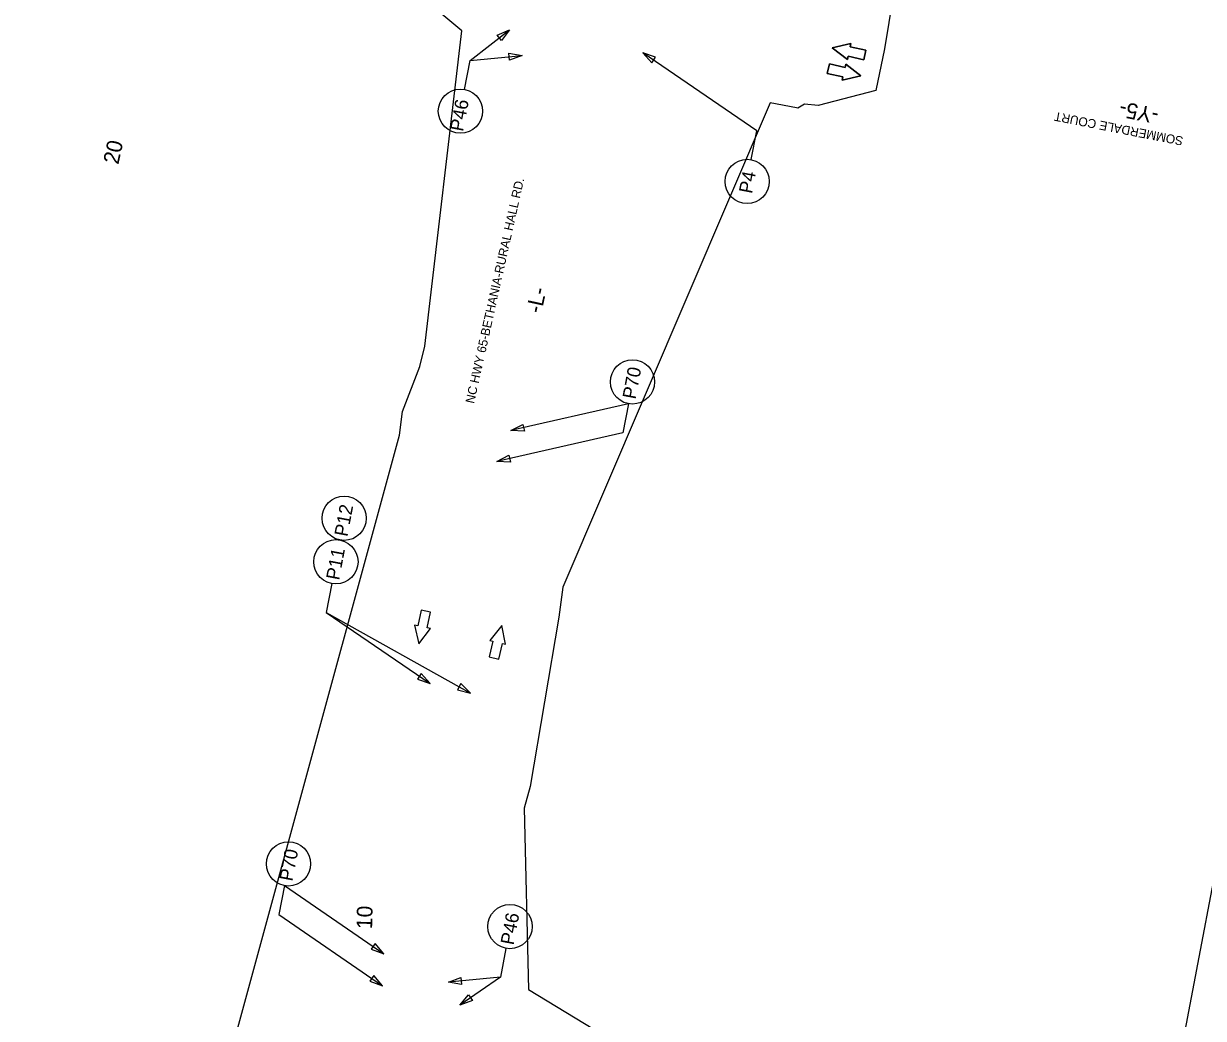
# Model space of a CAD drawing. Extents: x 1615680 to 1617075, y 898420 to 901168.
# Drawn here: x 1616168 to 1616696, y 900256 to 900701 of the extents above; entities that cross this region are included whole.
import ezdxf

# ---------------------------------------------------------------- set-up
doc = ezdxf.new("R2010")
doc.units = 0
for name, color, linetype in [('Default', 7, 'Continuous'), ('DEV DIRECTION OF TRAFFIC FLOW ARROW CELL', 7, 'Continuous'), ('Prop Horizontal Alignment Tick Label', 7, 'Continuous'), ('Scratch_Level_5', 7, 'Continuous'), ('Sheet Cross Section CELL', 7, 'Continuous')]:
    doc.layers.add(name, color=color, linetype=linetype)

msp = doc.modelspace()

# ---------------------------------------------------------------- linework, layer by layer
at = {"layer": 'Default'}
for p, q in [((1616367.82, 900684.55), (1616385.44, 900698.22)), ((1616438.6, 900531.14), (1616386.09, 900519.11)), ((1616303.52, 900437.85), (1616368.06, 900401.87)), ((1616284.79, 900315.8), (1616329.23, 900285.36)), ((1616381.37, 900274.83), (1616363.18, 900262.41))]:
    msp.add_line(p, q, dxfattribs=at)
for points in [[(1616379.91, 900695.89), (1616385.44, 900698.22), (1616381.82, 900693.44)], [(1616385.13, 900687.78), (1616391.05, 900686.79), (1616385.43, 900684.69)], [(1616450.77, 900686.01), (1616445.11, 900688), (1616449.02, 900683.44)], [(1616392.09, 900518.9), (1616386.09, 900519.11), (1616391.4, 900521.92)], [(1616385.84, 900505.08), (1616379.85, 900505.3), (1616385.15, 900508.11)], [(1616344.26, 900408.07), (1616349.92, 900406.08), (1616346.02, 900410.63)], [(1616362.24, 900403.34), (1616368.06, 900401.87), (1616363.75, 900406.05)], [(1616323.57, 900287.36), (1616329.23, 900285.36), (1616325.33, 900289.92)], [(1616323.07, 900273.08), (1616328.73, 900271.08), (1616324.82, 900275.64)], [(1616364.06, 900271.6), (1616358.14, 900272.59), (1616363.76, 900274.69)], [(1616368.84, 900264.4), (1616363.18, 900262.41), (1616367.09, 900266.96)]]:
    msp.add_lwpolyline(points, close=True, dxfattribs=at)
for points in [[(1616365.36, 900671.6), (1616367.82, 900684.55), (1616391.05, 900686.79)], [(1616493.56, 900640.2), (1616496.01, 900653.14), (1616445.11, 900688)], [(1616438.6, 900531.14), (1616436.14, 900518.2), (1616379.85, 900505.3)], [(1616305.98, 900450.79), (1616303.52, 900437.85), (1616349.92, 900406.08)], [(1616284.79, 900315.8), (1616282.33, 900302.85), (1616328.73, 900271.08)], [(1616383.82, 900287.77), (1616381.37, 900274.83), (1616358.14, 900272.59)]]:
    msp.add_lwpolyline(points, dxfattribs=at)
for centre in [(1616363.52, 900661.88), (1616491.71, 900630.48), (1616440.44, 900540.86), (1616311.52, 900479.95), (1616307.83, 900460.51), (1616286.63, 900325.52), (1616385.67, 900297.49)]:
    msp.add_circle(centre, 9.89, dxfattribs=at)
at = {"layer": 'DEV DIRECTION OF TRAFFIC FLOW ARROW CELL'}
for p, q in [((1616538.07, 900692.11), (1616529.71, 900690.22)), ((1616529.71, 900690.22), (1616538.07, 900692.11)), ((1616529.71, 900690.22), (1616536.49, 900684.98)), ((1616536.49, 900684.98), (1616529.71, 900690.22)), ((1616537.75, 900690.67), (1616538.07, 900692.11)), ((1616538.07, 900692.11), (1616537.75, 900690.67)), ((1616544.78, 900689.11), (1616537.75, 900690.67)), ((1616537.75, 900690.67), (1616544.78, 900689.11)), ((1616543.84, 900684.87), (1616544.78, 900689.11)), ((1616544.78, 900689.11), (1616543.84, 900684.87)), ((1616536.49, 900684.98), (1616536.81, 900686.42)), ((1616536.81, 900686.42), (1616536.49, 900684.98)), ((1616536.81, 900686.42), (1616543.84, 900684.87)), ((1616543.84, 900684.87), (1616536.81, 900686.42)), ((1616528.44, 900682.95), (1616527.5, 900678.7)), ((1616527.5, 900678.7), (1616528.44, 900682.95)), ((1616527.5, 900678.7), (1616534.53, 900677.14)), ((1616534.53, 900677.14), (1616527.5, 900678.7)), ((1616535.47, 900681.39), (1616528.44, 900682.95)), ((1616528.44, 900682.95), (1616535.47, 900681.39)), ((1616535.79, 900682.83), (1616535.47, 900681.39)), ((1616535.47, 900681.39), (1616535.79, 900682.83)), ((1616542.57, 900677.59), (1616535.79, 900682.83)), ((1616535.79, 900682.83), (1616542.57, 900677.59)), ((1616534.21, 900675.7), (1616542.57, 900677.59)), ((1616542.57, 900677.59), (1616534.21, 900675.7)), ((1616534.53, 900677.14), (1616534.21, 900675.7)), ((1616534.21, 900675.7), (1616534.53, 900677.14)), ((1616345.93, 900438.91), (1616344.44, 900431.87)), ((1616350.19, 900438.01), (1616345.93, 900438.91)), ((1616348.69, 900430.97), (1616350.19, 900438.01)), ((1616344.44, 900431.87), (1616342.99, 900432.17)), ((1616342.99, 900432.17), (1616344.96, 900423.83)), ((1616344.96, 900423.83), (1616350.14, 900430.66)), ((1616350.14, 900430.66), (1616348.69, 900430.97)), ((1616381.96, 900432.07), (1616376.62, 900425.37)), ((1616383.72, 900423.68), (1616381.96, 900432.07)), ((1616376.62, 900425.37), (1616378.05, 900425.02)), ((1616378.05, 900425.02), (1616376.39, 900418.02)), ((1616380.62, 900417.01), (1616382.28, 900424.02)), ((1616382.28, 900424.02), (1616383.72, 900423.68)), ((1616376.39, 900418.02), (1616380.62, 900417.01))]:
    msp.add_line(p, q, dxfattribs=at)
at = {"layer": 'Scratch_Level_5'}
for points in [[(1616598.93, 900968.63), (1616553.12, 900689.68), (1616549.22, 900671.08), (1616523.49, 900664.4), (1616517.29, 900664.94), (1616514.38, 900663.18), (1616513.71, 900663.29), (1616502.01, 900665.64), (1616409.34, 900449.1), (1616407.45, 900435.71), (1616394.68, 900360.06), (1616392.05, 900350.44), (1616393.93, 900269.36), (1616423.1, 900251.65)], [(1616364.12, 900697.77), (1616346.17, 900712.92)], [(1616273.84, 899841.42), (1616273.25, 899812.18), (1616273.25, 899811.36), (1616264.99, 899807.36), (1616258.95, 899802.9), (1616253.13, 899795.75), (1616247.48, 899786.63), (1616244, 899777.92), (1616242.54, 899778.39), (1616221.34, 899877.87), (1616220.94, 899877.94), (1616226.27, 899953.84), (1616231.37, 899979.34), (1616235.41, 899998.49), (1616168.21, 900084.42), (1616170.51, 900091.83), (1616174.76, 900111.37), (1616176.76, 900111.01), (1616234.19, 900143.08), (1616336.31, 900517.08), (1616337.63, 900527.64), (1616345.35, 900547.71), (1616347.66, 900556.85), (1616364.12, 900697.77)]]:
    msp.add_lwpolyline(points, dxfattribs=at)
at = {"layer": 'Sheet Cross Section CELL'}
msp.add_line((1616723.15, 900439.56), (1616559.31, 899576.61), dxfattribs=at)

# ---------------------------------------------------------------- texts
at = {"layer": 'Default'}
for s, height, rotation, p in [('P46', 6, 79.2494, (1616364.65, 900652.51)), ('SOMMERDALE COURT', 4, 168.9309, (1616686.9, 900650.36)), ('NC HWY 65-BETHANIA-RURAL HALL RD.', 4, 77.4143, (1616369.59, 900530.98)), ('P4', 6, 79.2493, (1616493.83, 900624.76)), ('P70', 6, 79.2493, (1616441.78, 900532.89)), ('P12', 6, 79.2493, (1616312.96, 900471.47)), ('P11', 6, 79.2493, (1616309.27, 900452.03)), ('P70', 6, 79.2494, (1616288.37, 900317.48)), ('P46', 6, 79.2494, (1616387.25, 900288.99))]:
    msp.add_text(s, height=height, rotation=rotation, dxfattribs=at).set_placement(p)
at = {"layer": 'Prop Horizontal Alignment Tick Label'}
for s, rotation, p in [('-Y5-', 168.742, (1616676.14, 900662.95)), ('20', 77.7098, (1616210.56, 900637.8)), ('-L-', 77.7098, (1616399.64, 900571.21)), ('10', 88.5681, (1616324.01, 900296.31))]:
    msp.add_text(s, height=7, rotation=rotation, dxfattribs=at).set_placement(p)

doc.saveas('drawing.dxf')
